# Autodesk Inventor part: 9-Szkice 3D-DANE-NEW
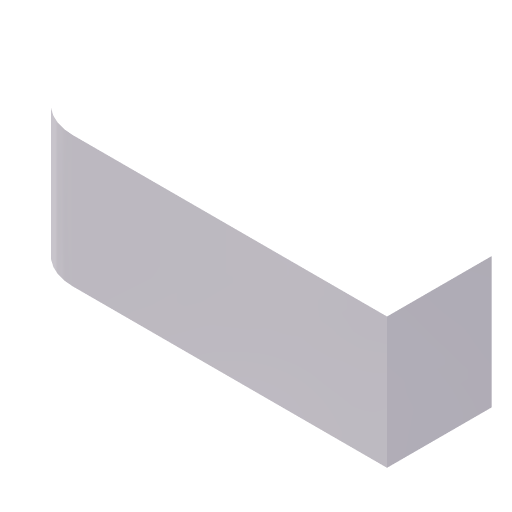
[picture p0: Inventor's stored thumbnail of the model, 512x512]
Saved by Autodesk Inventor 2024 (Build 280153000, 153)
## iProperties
Company: ATC
Created: 2023-03
Part Number: 9-Szkice 3D-DANE-NEW
Material: Kurs-AJ
Document SubType Name: Modeling
Designer: Andrzej Jaskulski
Density: 1 g/cm^3
Appearance: Kurs-AJ
Checked By: A.J.
Engr Approved By: Andrzej Jaskulski
Mfg Approved By: Andrzej Jaskulski
Authority: A.J.
Author: Andrzej Jaskulski
Title: A.J.: Kurs R2024-MEP
Revision Number: 1/24
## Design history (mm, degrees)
sketch "Podstawa"
  geometry: L1 (0, 0)-(140, 0); L2 (140, 0)-(140, 40); L3 (140, 40)-(0, 40); L4 (0, 40)-(0, 0)
  constraints: 8 end point, 2 parallel, 1 horizontal, 1 perpendicular, 1 other
  dimensions: "L1" = 140 distance of L1.start L1.end; "L2" = 40 distance of L1.end L2.end
extrude "Baza" new body sketch "Podstawa" taper "d3" = 0 deg; distance "Ha" = 50
node "Bryła1"
fillet "Zaokrąglenie" dims "d4" = 20
